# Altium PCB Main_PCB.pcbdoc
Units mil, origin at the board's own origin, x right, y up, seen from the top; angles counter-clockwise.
Board outline 4350.31 x 2530.27 mil, 2 copper layers (Top Layer, Bottom Layer); 37 components, 31 nets, 152 pads, 20 vias.
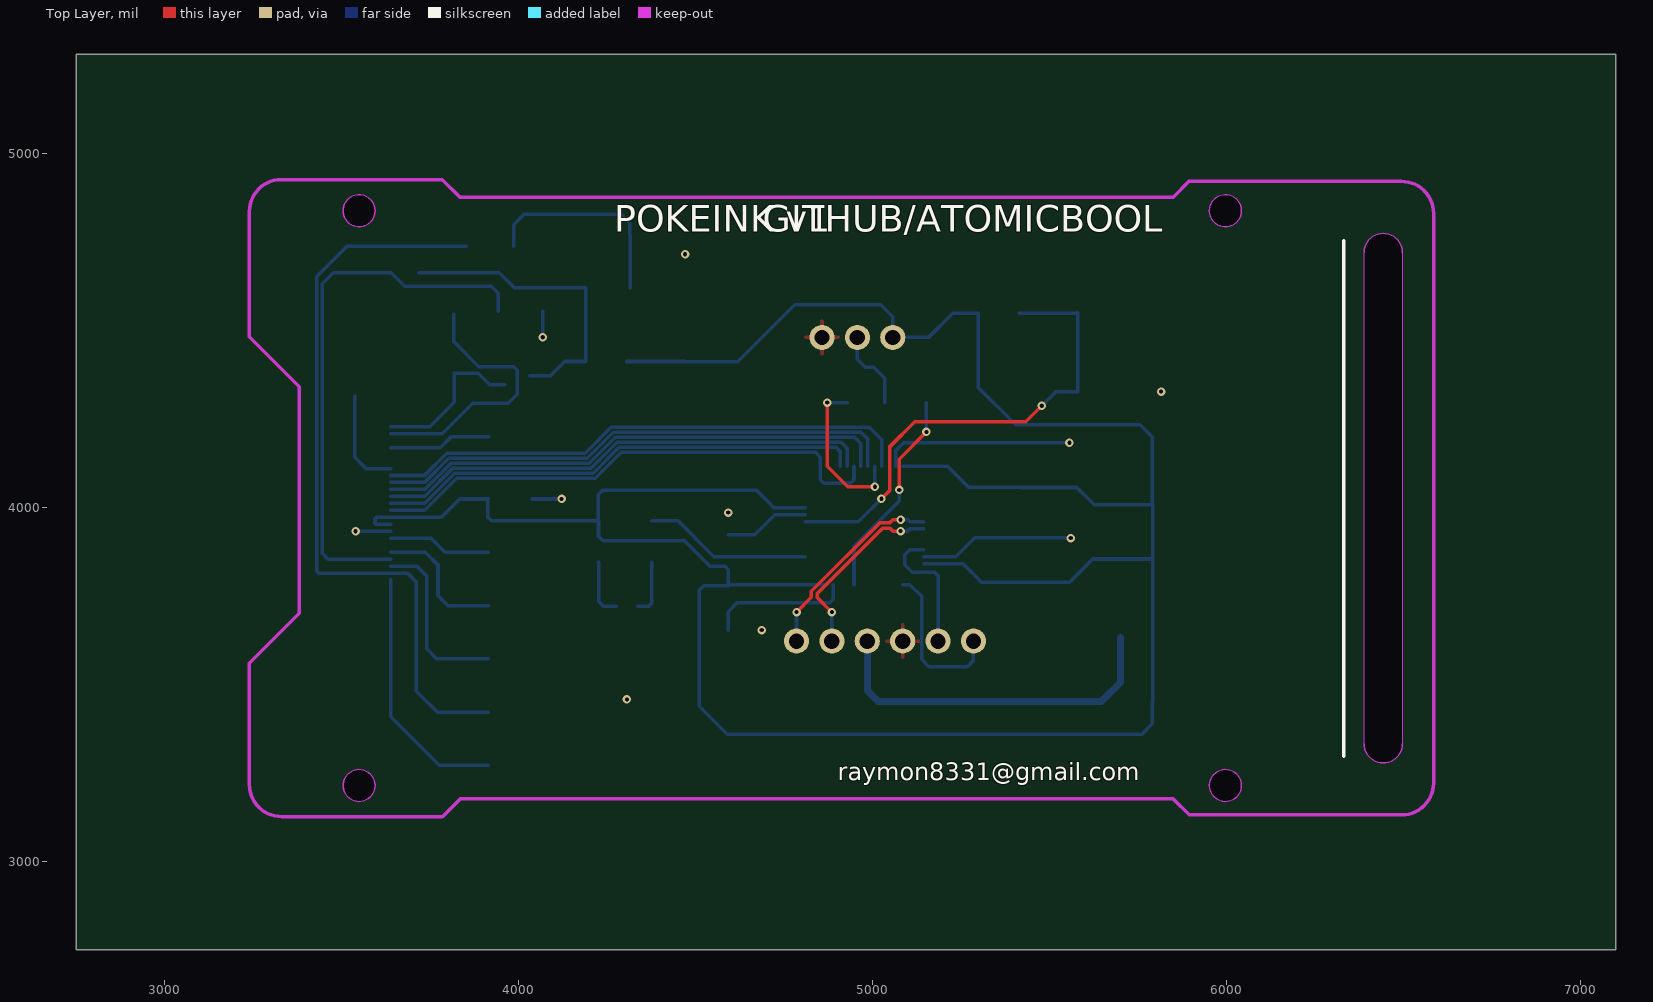
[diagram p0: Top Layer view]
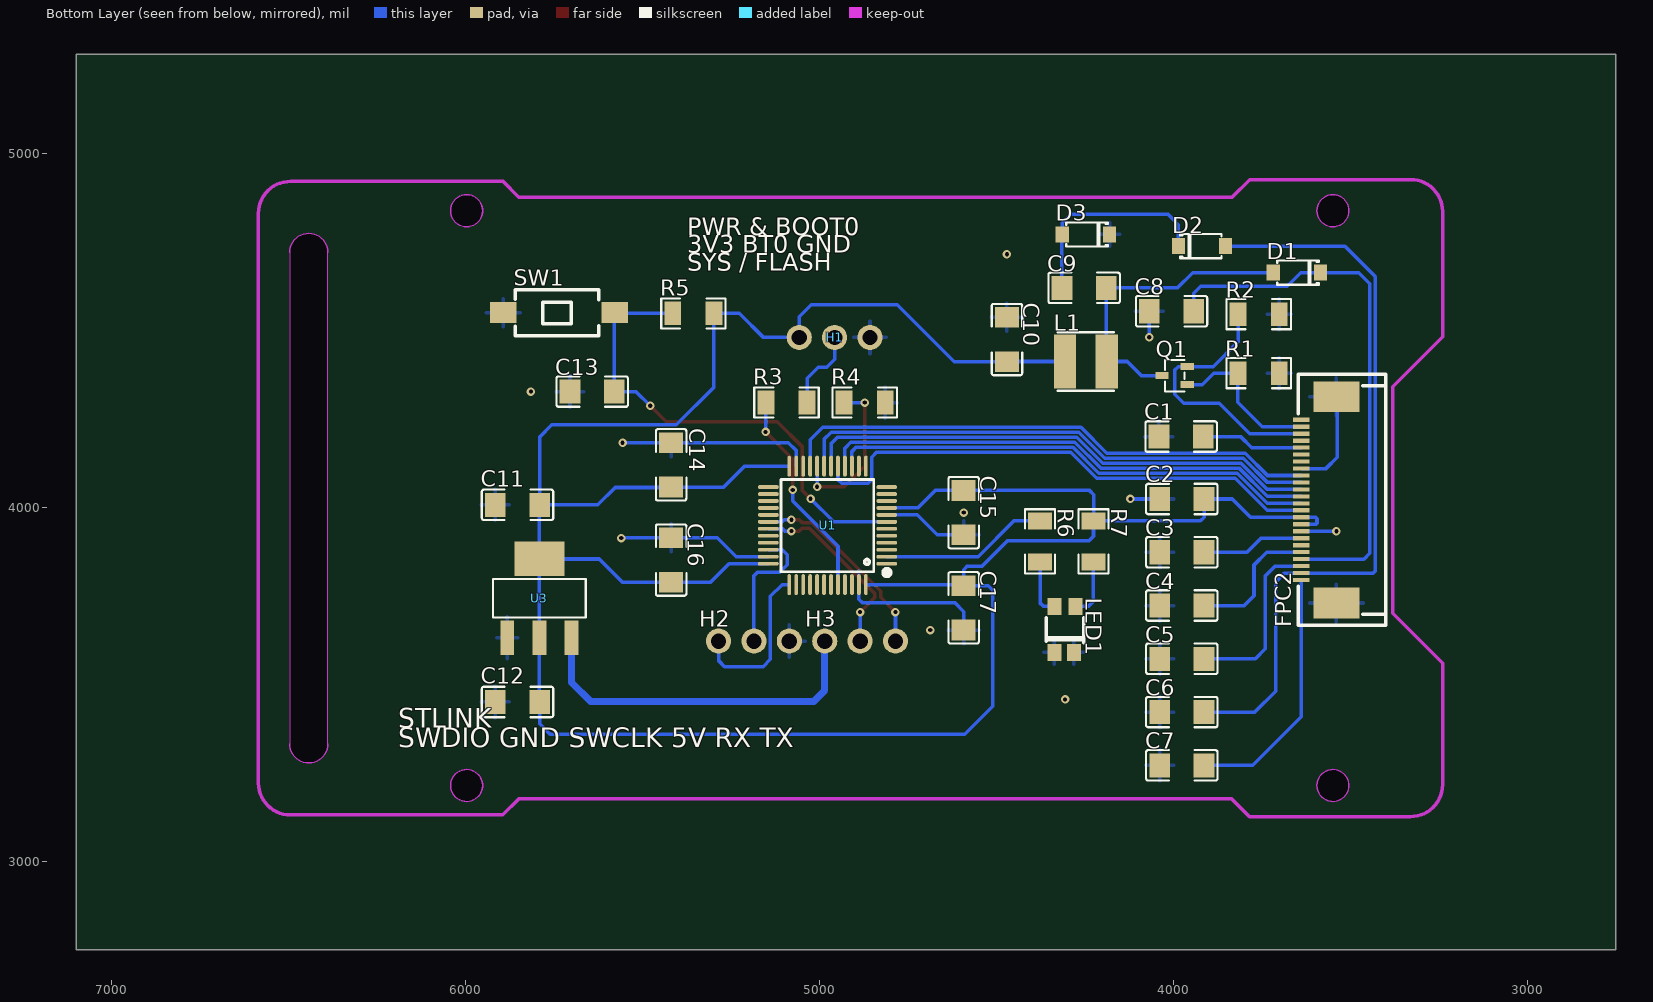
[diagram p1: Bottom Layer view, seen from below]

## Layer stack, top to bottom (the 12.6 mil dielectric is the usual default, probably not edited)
Top Layer: signal copper (thickness not stored)
Dielectric: dielectric 12.6, FR-4, Dk 4.8
Bottom Layer: signal copper (thickness not stored)

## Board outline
7100.31,2750 2750,2750 2750,5280.27 7100.31,5280.27
cut-out: 3594.58,4837.91 cw(c3549.31,4837.91) 3504.03,4837.91 cw(c3549.31,4837.91)
cut-out: 3594.58,3213.91 cw(c3549.31,3213.91) 3504.03,3213.91 cw(c3549.31,3213.91)
cut-out: 6042.57,4837.91 cw(c5997.29,4837.91) 5952.02,4837.91 cw(c5997.29,4837.91)
cut-out: 6042.57,3213.91 cw(c5997.29,3213.91) 5952.02,3213.91 cw(c5997.29,3213.91)
cut-out: 6443.05,4773.94 cw(c6443.05,4719.81) 6497.18,4719.81 6497.18,3332.01 cw(c6443.05,3332.01) 6443.05,3277.88 cw(c6443.05,3332.01) 6388.92,3332.01 6388.92,4719.81 cw(c6443.05,4719.81)

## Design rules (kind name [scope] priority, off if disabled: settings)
BoardOutlineClearance copperThickness1oz [All] p0: genericclearance=10 ignorepadtopadclearanceinfootprint=FALSE except(0: Arc-SplitContinuation Track-SplitContinuation SMDPad-SplitContinuation THPad-SplitContinuation Via-SplitContinuation Fill-SplitContinuation Poly-SplitContinuation Region-SplitContinuation Text-SplitContinuation; 6: Track-CutoutEdge SMDPad-CutoutEdge THPad-CutoutEdge Via-CutoutEdge Region-CutoutEdge; 11.8: Track-OutlineEdge SMDPad-OutlineEdge THPad-OutlineEdge Via-OutlineEdge Fill-OutlineEdge Region-OutlineEdge Poly-OutlineEdge Text-OutlineEdge Fill-CutoutEdge)
BoardOutlineClearance copperThickness2oz [All] p0: genericclearance=10 ignorepadtopadclearanceinfootprint=FALSE except(0: Arc-SplitContinuation Track-SplitContinuation SMDPad-SplitContinuation THPad-SplitContinuation Via-SplitContinuation Fill-SplitContinuation Poly-SplitContinuation Region-SplitContinuation Text-SplitContinuation; 6: Track-CutoutEdge SMDPad-CutoutEdge THPad-CutoutEdge Via-CutoutEdge Region-CutoutEdge; 11.8: Track-OutlineEdge SMDPad-OutlineEdge THPad-OutlineEdge Via-OutlineEdge Fill-OutlineEdge Region-OutlineEdge Poly-OutlineEdge Text-OutlineEdge Fill-CutoutEdge)
Clearance copperThickness1oz [(InNet('VCOM') OR InNet('PVGL') OR InNet('$1N1662') OR InNet('PVGH') OR InNet('$1N1618') OR InNet('$1N1584') OR InNet('GND') OR InNet('3V3') OR InNet('CS') OR InNet('DCX') OR InNet('RES') OR InNet('BUSY') OR InNet('$1N1465') OR InNet('RESE') OR InNet('GDR') OR InNet('$1N1889') OR InNet('$1N2921') OR InNet('NRST') OR InNet('BOOT1') OR InNet('BOOT0') OR InNet('$1N4223') OR InNet('5V') OR InNet('SDA') OR InNet('SCK') OR InNet('USART_TX') OR InNet('USART_RX') OR InNet('SWDIO') OR InNet('SWCLK') OR InNet('LED_MCU') OR InNet('$1N6084') OR InNet('$1N6080'))] p1: gap=7 ignorepadtopadclearanceinfootprint=FALSE except(4: Track-Track; 6: Track-SMDPad SMDPad-SMDPad Track-THPad SMDPad-THPad THPad-THPad Track-Via SMDPad-Via THPad-Via Via-Via SMDPad-Fill THPad-Fill Via-Fill Fill-Fill Track-Region SMDPad-Region THPad-Region Via-Region Region-Region Track-Poly SMDPad-Poly THPad-Poly Via-Poly Fill-Poly Region-Poly Poly-Poly Track-Text SMDPad-Text THPad-Text Via-Text Fill-Text Region-Text Poly-Text Text-Text; 6.9: Track-Hole SMDPad-Hole THPad-Hole Via-Hole Fill-Hole Region-Hole Poly-Hole Text-Hole Sheet-Hole; 11.8: Track-Fill Fill-Region Track-Sheet SMDPad-Sheet THPad-Sheet Via-Sheet Fill-Sheet Region-Sheet Poly-Sheet Text-Sheet)
Clearance copperThickness2oz [All] p1: gap=7 ignorepadtopadclearanceinfootprint=FALSE except(6: Track-SMDPad SMDPad-SMDPad Track-THPad SMDPad-THPad THPad-THPad Track-Via SMDPad-Via THPad-Via Via-Via SMDPad-Fill THPad-Fill Via-Fill Fill-Fill Track-Region SMDPad-Region THPad-Region Via-Region Region-Region Track-Poly SMDPad-Poly THPad-Poly Via-Poly Fill-Poly Region-Poly Poly-Poly Track-Text SMDPad-Text THPad-Text Via-Text Fill-Text Region-Text Poly-Text Text-Text; 6.9: Track-Hole SMDPad-Hole THPad-Hole Via-Hole Fill-Hole Region-Hole Poly-Hole Text-Hole Sheet-Hole; 8: Track-Track; 11.8: Track-Fill Fill-Region Track-Sheet SMDPad-Sheet THPad-Sheet Via-Sheet Fill-Sheet Region-Sheet Poly-Sheet Text-Sheet)
DiffPairsRouting differentialPair [All] p1: maxuncoupledlength=200 minlimit=6 maxlimit=6 mostfreqgap=6 toplayer_minwidth=5 toplayer_prefwidth=10 toplayer_maxwidth=100 bottomlayer_minwidth=5 bottomlayer_prefwidth=10 bottomlayer_maxwidth=100
PasteMaskExpansion pasteMaskExpansion [All] p1: expansion=0
PlaneConnect innerPlane [All] p1: planeconnectstyle=Relief reliefexpansion=20 reliefentries=4 reliefconductorwidth=10 reliefairgap=10
PolygonConnect copperRegion [All] p1: connectstyle=Relief reliefentries=4 reliefconductorwidth=10 polygonreliefangle="90 Angle" airgapwidth=10
RoutingVias viaSize [All] p1: viastyle="Through Hole" holewidth=12.0078 minholewidth=11.811 maxholewidth=248.0314 width=24.0158 minwidth=19.685 maxwidth=393.7008
SolderMaskExpansion solderMaskExpansion [All] p1: useseparateexpansions=TRUE expansion=2 expansionbottom=2
Width copperThickness1oz [All] p1: maxlimit=100 minlimit=5 preferedwidth=10
Width copperThickness2oz [All] p1: maxlimit=100 minlimit=8 preferedwidth=10

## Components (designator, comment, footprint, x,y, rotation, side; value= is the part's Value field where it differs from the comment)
C1 "CL31B105KAHNNNE" C1206 3978.31,4199.91 r180 bottom
C2 "CL31B105KAHNNNE" C1206 3976.31,4023.41 r0 bottom
C3 "CL31B105KAHNNNE" C1206 3976.31,3872.91 r0 bottom
C4 "CL31B105KAHNNNE" C1206 3976.31,3722.41 r0 bottom
C5 "CL31B105KAHNNNE" C1206 3976.31,3571.91 r0 bottom
C6 "CL31B105KAHNNNE" C1206 3976.31,3421.41 r0 bottom
C7 "CL31B105KAHNNNE" C1206 3976.31,3270.91 r0 bottom
C8 "CL31B105KAHNNNE" C1206 4005.31,4553.91 r180 bottom
C9 "1206B475K250NT" C1206 4252.31,4619.91 r0 bottom
C10 "1206B475K250NT" C1206 4470.31,4473.91 r90 bottom
C11 "CL31B104KCFNNNE" C1206 5853.31,4006.91 r180 bottom
C12 "CL31B104KCFNNNE" C1206 5853.31,3449.91 r180 bottom
C13 "CL31B104KCFNNNE" C1206 5642.31,4326.91 r0 bottom
C14 "CL31B104KCFNNNE" C1206 5419.31,4119.91 r270 bottom
C15 "CL31B104KCFNNNE" C1206 4592.72,3984.91 r90 bottom
C16 "CL31B104KCFNNNE" C1206 5419.31,3850.91 r270 bottom
C17 "CL31B104KCFNNNE" C1206 4592.72,3715.91 r270 bottom
D1 "MBR0530_C77336" SOD-123_L2.8-W1.8-LS3.7-RD 3651.31,4662.91 r0 bottom
D2 "MBR0530_C77336" SOD-123_L2.8-W1.8-LS3.7-RD 3919.31,4737.91 r180 bottom
D3 "MBR0530_C77336" SOD-123_L2.8-W1.8-LS3.7-RD 4247.31,4770.91 r0 bottom
FPC2 "AFC07-S24ECA-00" FPC-SMD_AFC07-S24ECA-00 3589.31,4020.91 r90 bottom
H1 "PZ254R-11-03P" HDR-TH_3P-P2.54-H-M-W10.4 4957.31,4479.91 r0 bottom
H2 "PZ254R-11-03P" HDR-TH_3P-P2.54-H-M-W10.4 5185.31,3621.91 r180 bottom
H3 "PZ254R-11-03P" HDR-TH_3P-P2.54-H-M-W10.4 4885.31,3621.91 r180 bottom
L1 "FNR4020S680MT" IND-SMD_L4.0-W4.0_FNR40XXS 4247.31,4411.91 r180 bottom
LED1 "TJ-S3227SW1TCGLC2R6B-A5" LED-SMD_4P-L3.2-W2.7_PD15-22C 4306.31,3654.91 r90 bottom
Q1 "SI1308EDL" SOT-323-3_L2.0-W1.3-P1.30-LS2.1-BR 3996.31,4371.91 r180 bottom
R1 "FRC1206J105 TS" R1206 3759.25,4378.91 r0 bottom
R2 "FRC1206J2R2 TS" R1206 3759.25,4545.65 r0 bottom
R3 "FRC1206J103 TS" R1206 5093.31,4295.91 r180 bottom
R4 "FRC1206J103 TS" R1206 4872.31,4295.91 r180 bottom
R5 "FRC1206J103 TS" R1206 5356.31,4547.91 r180 bottom
R6 "FRC1206J102 TS" R1206 4376.81,3903.41 r270 bottom
R7 "FRC1206J102 TS" R1206 4225.81,3903.41 r270 bottom
SW1 "TS-1101-C-W" SW-SMD_L6.0-W3.3-LS8.0 5736.31,4549.91 r180 bottom
U1 "STM32F103C8T6" LQFP-48_L7.0-W7.0-P0.50-LS9.0-BL 4977.31,3948.91 r90 bottom
U3 "AMS1117-3.3_C347222" SOT-223-4_L6.5-W3.5-P2.30-LS7.0-BR 5791.31,3742.91 r270 bottom

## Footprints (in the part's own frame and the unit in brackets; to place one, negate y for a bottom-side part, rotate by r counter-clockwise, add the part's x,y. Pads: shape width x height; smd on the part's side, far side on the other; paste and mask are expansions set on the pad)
C1206 [mm]
  rect 1.485x1.728 smd: 1(-1.593,0) 2(1.593,0)
  silkscreen extent -2.56,-1.09 2.56,1.09
FPC-SMD_AFC07-S24ECA-00 [mm]
  rect 0.3x1.2 smd: 1(5.75,1.266) 2(5.251,1.266) 3(4.75,1.266) 4(4.25,1.266) 5(3.75,1.266) 6(3.249,1.266) 7(2.749,1.266) 8(2.25,1.266) 9(1.751,1.266) 10(1.25,1.266) 11(0.75,1.266) 12(0.25,1.266) 13(-0.251,1.266) 14(-0.75,1.266) 15(-1.25,1.266) 16(-1.749,1.266) 17(-2.25,1.266) 18(-2.75,1.266) 19(-3.251,1.266) 20(-3.751,1.266) 21(-4.251,1.266) 22(-4.749,1.266) 23(-5.25,1.266) 24(-5.75,1.266)
  rect 2.2x3.3 smd: 25(-7.401,-1.266) 26(7.401,-1.259)
  silkscreen extent -9,-4.8 9,1.46
HDR-TH_3P-P2.54-H-M-W10.4 [mm]
  round 1.8 hole 1.1: 1(-2.54,0) 2(0,0) 3(2.54,0)
IND-SMD_L4.0-W4.0_FNR40XXS [mm]
  rect 1.6x3.9 smd: 1(-1.5,0) 2(1.5,0)
  silkscreen extent -2,-2.1 2,2.1
LED-SMD_4P-L3.2-W2.7_PD15-22C [mm]
  rect 1.2x1 smd: 1(-1.65,-0.636) 2(1.65,-0.763) 3(1.65,0.764) 4(-1.65,0.764)
  silkscreen extent -0.97,-1.35 0.84,1.35
LQFP-48_L7.0-W7.0-P0.50-LS9.0-BL [mm]
  oval 0.27x1.5 smd: 1(-2.75,-4.25) 2(-2.25,-4.25) 3(-1.75,-4.25) 4(-1.25,-4.25) 5(-0.75,-4.25) 6(-0.25,-4.25) 7(0.25,-4.25) 8(0.75,-4.25) 9(1.25,-4.25) 10(1.75,-4.25) 11(2.25,-4.25) 12(2.75,-4.25) 25(2.75,4.25) 26(2.25,4.25) 27(1.75,4.25) 28(1.25,4.25) 29(0.75,4.25) 30(0.25,4.25) 31(-0.25,4.25) 32(-0.75,4.25) 33(-1.25,4.25) 34(-1.75,4.25) 35(-2.25,4.25) 36(-2.75,4.25)
  oval 1.5x0.27 smd: 13(4.25,-2.75) 14(4.25,-2.25) 15(4.25,-1.75) 16(4.25,-1.25) 17(4.25,-0.75) 18(4.25,-0.25) 19(4.25,0.25) 20(4.25,0.75) 21(4.25,1.25) 22(4.25,1.75) 23(4.25,2.25) 24(4.25,2.75) 37(-4.25,2.75) 38(-4.25,2.25) 39(-4.25,1.75) 40(-4.25,1.25) 41(-4.25,0.75) 42(-4.25,0.25) 43(-4.25,-0.25) 44(-4.25,-0.75) 45(-4.25,-1.25) 46(-4.25,-1.75) 47(-4.25,-2.25) 48(-4.25,-2.75)
  silkscreen extent -3.59,-4.46 3.3,3.34
R1206 [mil]
  rect 47.54x66.97 smd: 1(-58.22,0) 2(58.22,0)
  silkscreen extent -91,-42 91,42
SOD-123_L2.8-W1.8-LS3.7-RD [mm]
  rect 0.95x1.15 smd: 1(-1.692,0) 2(1.692,0)
  silkscreen extent -1.58,-0.87 1.41,0.87
SOT-223-4_L6.5-W3.5-P2.30-LS7.0-BR [mm]
  rect 2.47x0.98 smd: 1(2.835,-2.3) 2(2.835,0) 3(2.835,2.3)
  rect 2.47x3.6 smd: 4(-2.835,0)
  silkscreen extent -1.37,-3.33 1.37,3.33
SOT-323-3_L2.0-W1.3-P1.30-LS2.1-BR [mm]
  rect 0.936x0.5 smd: 1(0.898,-0.65) 2(0.898,0.65) 3(-0.898,0)
  silkscreen extent -0.7,-1.13 0.7,1.13
SW-SMD_L6.0-W3.3-LS8.0 [mm]
  rect 1.9x1.5 smd: 1(-4,0) 2(4,0)
  silkscreen extent -3.14,-1.67 2.86,1.63

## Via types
v1: diameter 24.02, hole 12.01, Top Layer to Bottom Layer, 20 vias

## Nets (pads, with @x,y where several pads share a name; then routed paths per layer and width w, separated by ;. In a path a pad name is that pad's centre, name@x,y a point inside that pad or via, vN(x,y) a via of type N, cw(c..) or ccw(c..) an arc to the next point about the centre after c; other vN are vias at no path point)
3V3: C2.1 C10.1 C11.2 C12.2 C14.2 C15.2 C16.2 C17.1 FPC2.15 FPC2.16 H1.3 L1.1 R5.2 R7.1 U1.9 U1.24 U1.36 U1.48 U3.2 U3.4 | length 8142.8
  Bottom Layer w10: FPC2.16@3639.32,3952.01 3597.21,3952.01 3594.31,3954.91 3594.31,3967.91 3598.09,3971.7 3638.15,3971.7 3782.09,3971.7 3833.81,4023.41 C2.1 3913.31,4023.11 3913.31,3971.91 3923.59,3961.63 R7.1 ; L1.1 4469.61,4411.91 C10.1 4619.61,4411.21 4780.31,4571.91 5023.31,4571.91 5057.31,4537.91 H1.3 5158.31,4479.91 5226.31,4547.91 R5.2 5298.31,4547.69 5298.31,4338.91 5404.31,4232.91 5756.31,4232.91 5790.61,4198.61 C11.2 ; U1.9 4722.1,3998.12 4672.61,4047.61 C15.2 4237.01,4047.61 4225.31,4035.91 4225.31,3962.13 R7.1 ; U1.48 4595.7,3781.59 C17.1 ; U1.24 5211.99,4116.23 5271.31,4056.91 5419.01,4056.91 C14.2 5420.61,4055.91 5577.31,4055.91 5626.31,4006.91 C11.2 ; U1.36 5255.58,3840.64 5308.01,3788.21 C16.2 5556.61,3788.21 5622.31,3853.91 5790.7,3853.91 U3.4 ; R7.1 4225.81,3918.41 4239.31,3904.91 4469.31,3904.91 4540.31,3833.91 4582.31,3833.91 4592.72,3823.5 C17.1 ; C17.1 4523.01,3778.61 4510.31,3765.91 4510.31,3437.91 4589.31,3358.91 5761.31,3358.91 5790.61,3388.21 C12.2 5791.31,3450.61 U3.2 U3.4 ; C11.2 5791.31,4006.21 U3.4
5V: H3.1 U3.3 | length 1015.8
  Bottom Layer w20: H3.1@4985.31,3620.91 4985.31,3481.91 5016.31,3450.91 5646.31,3450.91 5700.76,3505.36 U3.3
$1N1465: C1.2 FPC2.5 | length 289.3
  Bottom Layer w10: FPC2.5@3639.32,4168.55 3778.94,4168.55 3810.31,4199.91 C1.2
$1N1584: C3.1 FPC2.18 | length 290.7
  Bottom Layer w10: FPC2.18@3639.32,3912.64 3752.58,3912.64 3792.31,3872.91 C3.1
$1N1618: C4.1 FPC2.20 | length 387.7
  Bottom Layer w10: FPC2.20@3639.32,3873.27 3735.95,3873.27 3772.31,3836.91 3772.31,3749.91 3799.81,3722.41 C4.1
$1N1662: C5.1 FPC2.22 | length 503.5
  Bottom Layer w10: FPC2.22@3639.33,3833.91 3712.31,3833.91 3740.31,3805.91 3740.31,3599.91 3768.31,3571.91 C5.1
$1N1889: C9.2 D2.1 D3.2 | length 595.4
  Bottom Layer w10: D2.1 3985.94,4798.54 4015.31,4827.91 4290.31,4827.91 4313.94,4804.28 D3.2 4315.01,4769.84 C9.2
$1N2921: C9.1 D1.2 L1.2 Q1.3 | length 871.2
  Bottom Layer w10: D1.2 3945.31,4662.91 3988.31,4619.91 C9.1 4189.61,4413.27 L1.2 4130.31,4411.91 4090.31,4371.91 Q1.3
$1N4223: H1.2 R3.2 | length 230.3
  Bottom Layer w10: H1.2 4957.31,4417.91 4979.59,4395.64 5003.59,4395.64 5035.09,4364.13 R3.2
$1N6080: LED1.2 R7.2 | length 167.2
  Bottom Layer w10: R7.2 4226.31,3844.69 4226.31,3733.91 4240.35,3719.87 LED1.2
$1N6084: LED1.3 R6.2 | length 160.1
  Bottom Layer w10: LED1.3 4367.27,3719.87 ; 4367.31,3719.91 4376.81,3729.41 R6.2
BOOT0: R3.1 U1.44 | length 599.4
  Top Layer w10: v1(5075.31,4048.91) 5075.31,4135.91 v1(5152.31,4212.91)
  Bottom Layer w10: U1.44 4947.78,3890.38 5075.31,4017.91 v1(5075.31,4048.91) ; R3.1 5151.53,4213.69 v1(5152.31,4212.91)
BOOT1: R4.1 U1.20 | length 453.1
  Top Layer w10: v1(4872.31,4295.91) 4872.31,4115.91 4930.31,4057.91 v1(5006.84,4057.91)
  Bottom Layer w10: v1@4874.31,4295.91 R4.1 ; v1(5006.84,4057.91) U1.20
BUSY: FPC2.9 U1.21 | length 1532.6
  Bottom Layer w10: FPC2.9@3639.32,4089.81 3734.2,4089.81 3797.31,4152.91 4188.31,4152.91 4261.31,4225.91 4991.31,4225.91 5026.52,4190.7 U1.21
CS: FPC2.12 U1.16 | length 1410
  Bottom Layer w10: FPC2.12@3639.32,4030.75 3734.61,4030.75 3814.73,4110.87 4205.73,4110.87 4278.73,4183.87 4911.31,4183.87 4928.1,4167.08 U1.16
DCX: FPC2.11 U1.18 | length 1460.2
  Bottom Layer w10: FPC2.11@3639.32,4050.44 3734.48,4050.44 3808.92,4124.88 4199.92,4124.88 4272.92,4197.88 4949.31,4197.88 4967.47,4179.72 U1.18
GDR: FPC2.2 Q1.1 R1.2 | length 447
  Bottom Layer w10: FPC2.2@3639.32,4227.61 3749,4227.61 3818.31,4296.91 3818.31,4378.07 R1.2 3886.31,4378.91 3918.9,4346.32 Q1.1
GND: C1.1 C2.2 C3.2 C4.2 C5.2 C6.2 C7.2 C8.1 C10.2 C11.1 C12.1 C13.2 C14.1 C15.1 C16.1 C17.2 D3.1 FPC2.8 FPC2.17 FPC2.25 FPC2.26 H1.1 H2.3 LED1.1 LED1.4 R1.1 R2.1 R4.2 SW1.1 U1.8 U1.23 U1.35 U1.47 U3.1 | length 2170.4
  Bottom Layer w10: FPC2.26@3537.94,4313.83 3537.31,4313.2 3537.31,4140.91 3568.72,4109.5 FPC2.8@3639.32,4109.5 ; v1(3539.31,3932.33) FPC2.17@3639.32,3932.33 ; C2.2 v1(4121.31,4023.41) ; v1(4068.01,4480.7) C8.1 ; C17.2 4592.31,3653.62 4592.31,3704.91 4618.31,3730.91 4879.31,3730.91 4888.73,3740.33 U1.47 ; C15.1 4667.61,3922.21 4723.84,3978.44 U1.8 ; U1.23 5065.89,4160.49 5088.01,4182.61 C14.1 v1(5556.38,4182.61) ; U1.35 5235.73,3860.33 5289.01,3913.61 C16.1 5559.61,3913.61 v1(5560.31,3912.91)
  other v1: 4306.31,3457.19 4687.14,3653.22 4592.72,3984.91 5815.31,4326.91 4470.31,4714.91
LED_MCU: R6.1 U1.2 | length 475.1
  Bottom Layer w10: R6.1 4450.59,3961.63 4551.89,3860.33 U1.2
NRST: C13.1 R5.1 SW1.2 U1.7 | length 1383.2
  Top Layer w10: v1(5025.31,4023.91) 5049.31,4047.91 5049.31,4171.91 5119.31,4241.91 5433.31,4241.91 v1(5478.31,4286.91)
  Bottom Layer w10: U1.7 4960.15,3958.75 v1(5025.31,4023.91) ; R5.1 5576.83,4547.91 SW1.2 5579.61,4549.13 C13.1 5518.31,4326.91 v1(5478.31,4286.91)
PVGH: C8.2 D1.1 FPC2.21 | length 1547.8
  Bottom Layer w10: FPC2.21@3639.32,3853.59 3461.63,3853.59 3445.31,3869.91 3445.31,4631.91 3476.31,4662.91 D1.1 3640.31,4662.91 3678.31,4624.91 3922.31,4624.91 3942.61,4604.61 C8.2
PVGL: C6.1 D2.2 FPC2.23 | length 2121.4
  Bottom Layer w10: D2.2 3515.31,4737.91 3429.31,4651.91 3429.31,3819.91 3435,3814.22 3638.15,3814.22 3686,3814.22 3711.31,3788.91 3711.31,3479.91 3769.81,3421.41 C6.1
RES: FPC2.10 U1.19 | length 1490.6
  Bottom Layer w10: FPC2.10@3639.32,4070.13 3734.35,4070.13 3803.11,4138.9 4194.11,4138.9 4267.11,4211.9 4967.32,4211.9 4987.15,4192.07 U1.19
RESE: FPC2.3 Q1.2 R2.2 | length 761.9
  Bottom Layer w10: FPC2.3 3784.33,4207.94 3870.31,4293.91 3971.31,4293.91 3996.31,4318.91 3996.31,4387.91 3986.72,4397.5 Q1.2 3887.72,4397.5 3817.47,4467.75 R2.2
SCK: FPC2.13 U1.15 | length 1380.9
  Bottom Layer w10: FPC2.13@3639.32,4011.07 3734.75,4011.07 3819.95,4096.27 4210.95,4096.27 4283.95,4169.27 4896.95,4169.27 4908.41,4157.81 U1.15
SDA: FPC2.14 U1.17 | length 1491.9
  Bottom Layer w10: FPC2.14@3639.32,3991.38 3734.88,3991.38 3825.76,4082.25 4216.76,4082.25 4289.76,4155.25 4838.97,4155.25 4852.74,4141.48 4852.74,4077.91 4862.74,4067.91 4937.31,4067.91 4947.78,4078.38 U1.17
SWCLK: H2.1 U1.37 | length 462
  Bottom Layer w10: U1.37 5105.63,3781.59 5138.89,3748.33 5138.89,3570.33 5159.31,3549.91 5268.31,3549.91 5285.31,3566.91 H2.1
SWDIO: H2.2 U1.34 | length 379
  Bottom Layer w10: U1.34 5105.41,3880.01 5091.31,3865.91 5091.31,3837.91 5112.31,3816.91 5175.31,3816.91 5185.31,3806.91 H2.2
USART_RX: H3.2 U1.31 | length 536.2
  Top Layer w10: v1(4885.31,3703.81) 4843.31,3745.81 4843.31,3755.81 5028.41,3940.91 5049.3,3940.91 5057.3,3932.91 v1(5079.31,3932.91)
  Bottom Layer w10: H3.2@4885.31,3620.91 v1(4885.31,3703.81) ; v1(5079.31,3932.91) 5098.31,3932.91 5104.47,3939.07 U1.31
USART_TX: H3.3 U1.30 | length 562.7
  Top Layer w10: v1(4785.31,3703.81) 4827.31,3745.81 4827.31,3762.44 5021.79,3956.91 5049.3,3956.91 5057.3,3964.91 v1(5079.31,3964.91)
  Bottom Layer w10: H3.3@4785.31,3620.91 v1(4785.31,3703.81) ; v1(5079.31,3964.91) 5099.31,3964.91 5105.47,3958.75 U1.30
VCOM: C7.1 FPC2.24 | length 717.7
  Bottom Layer w10: FPC2.24@3639.32,3794.53 3639.32,3407.9 3776.31,3270.91 C7.1
pads on no net: FPC2.1 FPC2.4 FPC2.6 FPC2.7 FPC2.19 U1.1 U1.3 U1.4 U1.5 U1.6 U1.10 U1.11 U1.12 U1.13 U1.14 U1.22 U1.25 U1.26 U1.27 U1.28 U1.29 U1.32 U1.33 U1.38 U1.39 U1.40 U1.41 U1.42 U1.43 U1.45 U1.46

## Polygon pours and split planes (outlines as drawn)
GND on Top Layer (solid, remove dead copper, pour order 0): 3074.09,5013 6818.34,5013 6818.34,3000 3074.09,3000
GND on Bottom Layer (solid, remove dead copper, pour order 2): 3000,5030.27 6697.99,5030.27 6697.99,3017.27 3000,3017.27

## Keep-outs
Board Outline Layer:
  circle w1: c3549.31,4837.91 r45.28
  region: 3594.58,4837.91 cw(c3549.31,4837.91) 3504.03,4837.91 cw(c3549.31,4837.91)
  circle w1: c3549.31,3213.91 r45.28
  region: 3594.58,3213.91 cw(c3549.31,3213.91) 3504.03,3213.91 cw(c3549.31,3213.91)
  circle w1: c5997.29,4837.91 r45.28
  region: 6042.57,4837.91 cw(c5997.29,4837.91) 5952.02,4837.91 cw(c5997.29,4837.91)
  circle w1: c5997.29,3213.91 r45.28
  region: 6042.57,3213.91 cw(c5997.29,3213.91) 5952.02,3213.91 cw(c5997.29,3213.91)
  region: 6443.05,4773.94 cw(c6443.05,4719.81) 6497.18,4719.81 6497.18,3332.01 cw(c6443.05,3332.01) 6443.05,3277.88 cw(c6443.05,3332.01) 6388.92,3332.01 6388.92,4719.81 cw(c6443.05,4719.81)
  lines w1: 6388.92,3332.01 ccw(c6443.05,3332.01) 6443.05,3277.88 ccw(c6443.05,3332.01) 6497.18,3332.01 6497.18,4719.81 ccw(c6443.05,4719.81) 6443.05,4773.94 ccw(c6443.05,4719.81) 6388.92,4719.81 6388.92,3332.01
  lines w10: 3239.31,4835.59 3239.31,4482.15 3380.54,4340.91 3380.54,3700.91 3239.31,3559.68 3239.31,3215.91 ccw(c3329.86,3216.53) 3330.48,3125.98 3784.96,3125.98 3834.89,3175.91 5849.89,3175.91 5894.89,3130.91 6264.6,3130.94 6494.93,3130.94 ccw(c6495.28,3221.17) 6585.5,3220.82 ; 3239.31,4835.91 cw(c3329.57,4835.59) 3329.89,4925.85 3784.37,4925.85 3834.31,4875.91 5849.31,4875.91 5894.31,4920.91 6264.02,4920.88 6494.34,4920.88 cw(c6494.99,4830.36) 6585.5,4831.01 ; 6585.77,3220.82 6585.77,4831.01

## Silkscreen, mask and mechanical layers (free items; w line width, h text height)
Top Silkscreen Layer:
  lines w10: 6331.98,3295.91 6331.98,4752.61
  text "POKEINK v1" at 4270.31,4777.91 h75
  text "GITHUB/ATOMICBOOL" at 4689.31,4777.91 h75
  text "raymon8331@gmail.com" at 4902.31,3228.91 h50
Bottom Silkscreen Layer:
  text "PWR & BOOT0" at 5373.31,4768.91 h50
  text "3V3 BT0 GND" at 5373.31,4718.91 h50
  text "SYS / FLASH" at 5373.31,4668.91 h50
  text "STLINK" at 6190.31,3376.91 h55
  text "SWDIO GND SWCLK 5V RX TX" at 6190.31,3321.91 h55
Mechanical Layer:
  circle w1: c3549.31,4837.91 r45.28
  circle w1: c3549.31,3213.91 r45.28
  circle w1: c5997.29,4837.91 r45.28
  circle w1: c5997.29,3213.91 r45.28
  lines w1: 6388.92,3332.01 ccw(c6443.05,3332.01) 6443.05,3277.88 ccw(c6443.05,3332.01) 6497.18,3332.01 6497.18,4719.81 ccw(c6443.05,4719.81) 6443.05,4773.94 ccw(c6443.05,4719.81) 6388.92,4719.81 6388.92,3332.01
Mech6:
  circle w10: c3549.31,4837.91 r61.02
  circle w10: c3549.31,3213.91 r61.02
  circle w10: c5997.29,4837.91 r61.02
  circle w10: c5997.29,3214.91 r61.02
  lines w10: 3250.17,3295.91 6360.4,3295.91 6360.4,4752.61 3250.17,4752.61 3250.17,3295.91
